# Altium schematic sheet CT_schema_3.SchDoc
size 313 x 200 mm
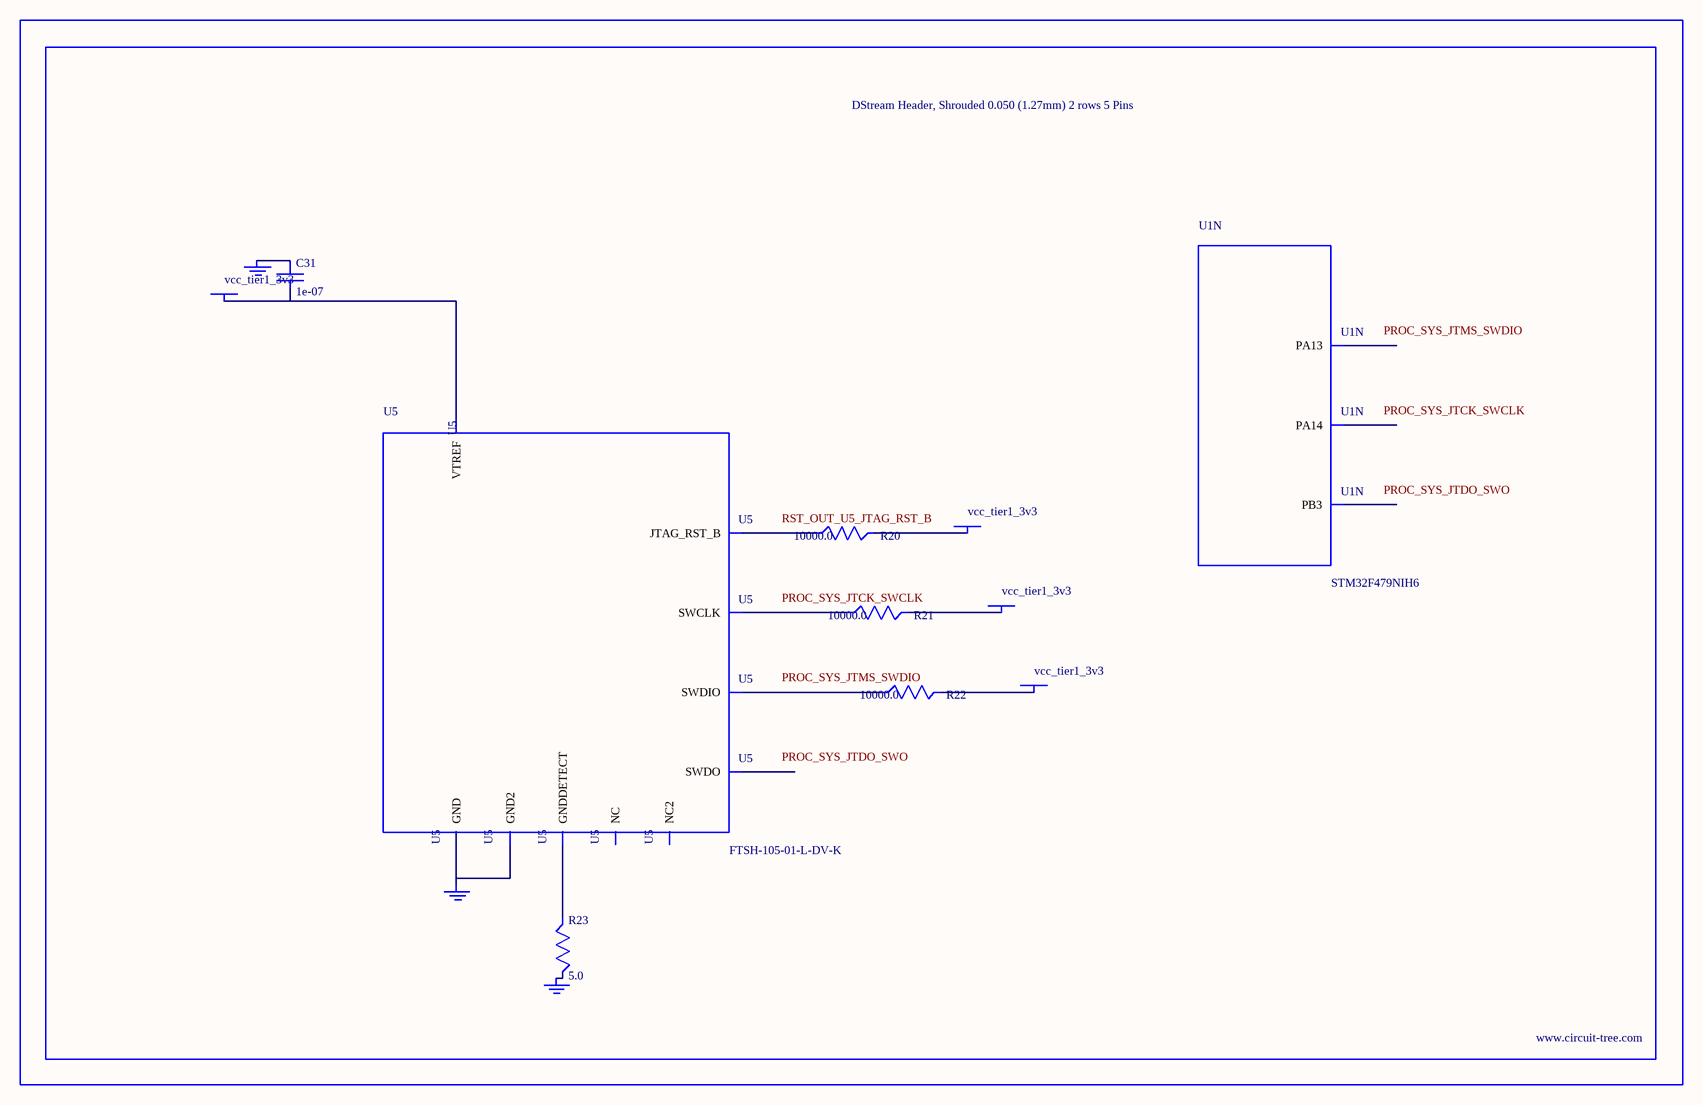
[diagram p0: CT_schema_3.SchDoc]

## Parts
BORDER2  (no value)
C31  1e-07  [C0402]
GND_INSTANCE_2_0  (no value)
GND_INSTANCE_2_1  (no value)
GND_INSTANCE_2_2  (no value)
POWER_INSTANCE_2_0  vcc_tier1_3v3
POWER_INSTANCE_2_1  vcc_tier1_3v3
POWER_INSTANCE_2_2  vcc_tier1_3v3
POWER_INSTANCE_2_3  vcc_tier1_3v3
R20  10000.0  [R0603]
R21  10000.0  [R0603]
R22  10000.0  [R0603]
R23  5.0  [R0603]
U1  STM32F479NIH6  [TFBGA216]  (part N of 17)
U5  FTSH-105-01-L-DV-K  [SAMTEC_FTSH-105-01-L-DV-K]

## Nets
NetC31_1: C31.1 GND_INSTANCE_2_0.0(GND)
NetC31_2: C31.2 POWER_INSTANCE_2_0.0(PWR) U5.1(VTREF)
NetGND_INSTANCE_2_1_0: GND_INSTANCE_2_1.0(GND) R23.2
NetGND_INSTANCE_2_2_0: GND_INSTANCE_2_2.0(GND) U5.3(GND) U5.5(GND2)
NetPOWER_INSTANCE_2_1_0: POWER_INSTANCE_2_1.0(PWR) R22.2
NetPOWER_INSTANCE_2_2_0: POWER_INSTANCE_2_2.0(PWR) R21.2
NetPOWER_INSTANCE_2_3_0: POWER_INSTANCE_2_3.0(PWR) R20.2
NetR20_1: R20.1 U5.10(JTAG_RST_B)
NetR21_1: R21.1 U5.4(SWCLK)
NetR22_1: R22.1 U5.2(SWDIO)
NetR23_1: R23.1 U5.9(GNDDETECT)

Not connected (* = marked no-connect by the designer): U1 A10(PB3) A14(PA14) A15(PA13); U5 6(SWDO) 7(NC) 8(NC2)

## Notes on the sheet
- Labels drawn without touching a wire or pin: PROC_SYS_JTCK_SWCLK, PROC_SYS_JTDO_SWO, PROC_SYS_JTMS_SWDIO, RST_OUT_U5_JTAG_RST_B

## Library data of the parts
BORDER2 = BORDER_PAGE2
C31 = C0402C104K3RACTU
GND_INSTANCE_2_0-GND_INSTANCE_2_2 = GND
POWER_INSTANCE_2_0-POWER_INSTANCE_2_3 = PWR
R20-R22 = RC0603JR-0710KL
R23 = ERJ-3GEYJ5R1V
